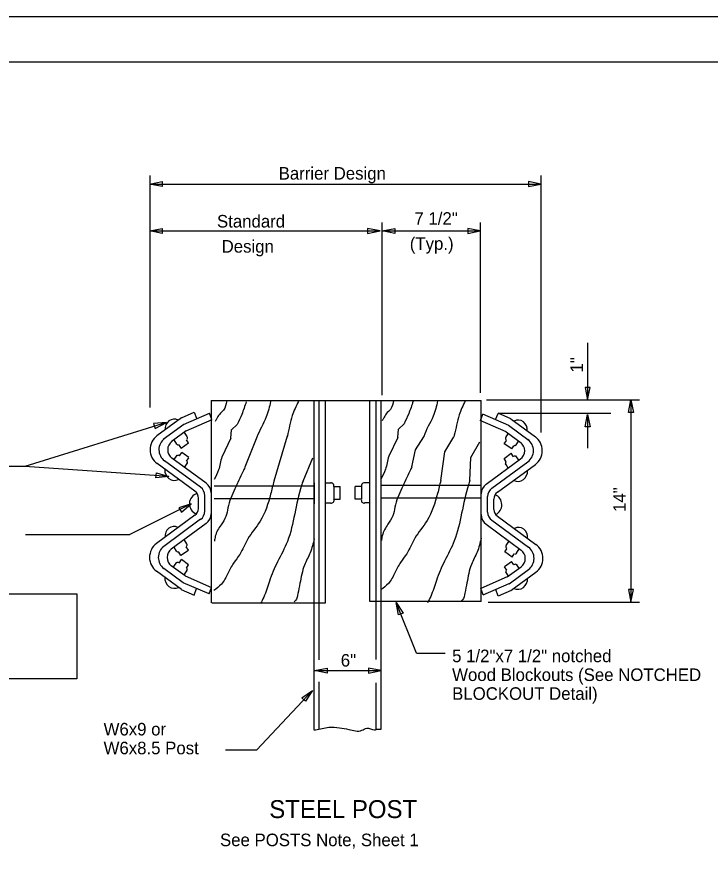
# Model space of a CAD drawing. Extents: x 0 to 34, y 0 to 22.
# Drawn here: x 11.64 to 19.37, y 12.6 to 22 of the extents above; entities that cross this region are included whole.
import ezdxf

# ---------------------------------------------------------------- set-up
doc = ezdxf.new("R2010")
doc.units = 0
for name, color, linetype in [('SH_Border', 7, 'Continuous'), ('SH_Cut_Line', 7, 'Continuous'), ('ST_Details', 7, 'Continuous'), ('ST_Text', 7, 'Continuous')]:
    doc.layers.add(name, color=color, linetype=linetype)

msp = doc.modelspace()

# ---------------------------------------------------------------- linework, layer by layer
at = {"layer": 'SH_Border'}
msp.add_lwpolyline([(2, 21.5), (33.5, 21.5), (33.5, 0.5), (2, 0.5)], close=True, dxfattribs=at)
at = {"layer": 'SH_Cut_Line'}
msp.add_lwpolyline([(0, 0), (34, 0), (34, 22), (0, 22)], close=True, dxfattribs=at)
at = {"layer": 'ST_Details'}
for p, q in [((13.8045, 17.7204), (16.8155, 17.7204)), ((13.8045, 17.7204), (13.8045, 15.4639)), ((14.9532, 15.4641), (14.9532, 17.7132)), ((15.0099, 15.4641), (15.0099, 17.7132)), ((15.0807, 15.4641), (15.0807, 17.7132)), ((15.5737, 15.4784), (15.5737, 17.7179)), ((15.6445, 15.4784), (15.6445, 17.7179)), ((15.7012, 15.4784), (15.7012, 17.7179)), ((16.8112, 17.7204), (16.8112, 15.4782)), ((13.4719, 17.5269), (13.6158, 17.5897)), ((13.6433, 17.5196), (13.6163, 17.5889)), ((13.4722, 17.5266), (13.1992, 17.3266)), ((13.4967, 17.4539), (13.7861, 17.5802)), ((13.5258, 17.3834), (13.8154, 17.5096)), ((13.8122, 17.5101), (13.7852, 17.5792)), ((17.0938, 17.3726), (16.8043, 17.4989)), ((16.8074, 17.4992), (16.8344, 17.5686)), ((17.1231, 17.4431), (16.8336, 17.5694)), ((16.9764, 17.5089), (17.0034, 17.5781)), ((17.1478, 17.5161), (17.0038, 17.5789)), ((17.1475, 17.5157), (17.4204, 17.3157)), ((13.4992, 17.4554), (13.2692, 17.2867)), ((14.0938, 17.4547), (14.0315, 17.3941)), ((15.8855, 17.3072), (15.8937, 17.4012)), ((15.9561, 17.4619), (15.8937, 17.4012)), ((17.1205, 17.4446), (17.3506, 17.2759)), ((13.525, 17.3829), (13.3583, 17.2607)), ((13.5364, 17.3182), (13.5062, 17.3656)), ((14.0233, 17.3001), (14.0315, 17.3941)), ((14.3129, 17.3119), (14.1808, 16.9761)), ((14.6532, 17.3251), (14.5026, 16.8231)), ((15.8855, 17.3072), (15.7845, 17.1011)), ((17.0891, 17.3096), (17.1192, 17.3569)), ((17.0947, 17.3721), (17.2614, 17.2499)), ((13.4207, 17.2357), (13.3915, 17.2814)), ((13.4693, 17.1892), (13.4462, 17.2256)), ((13.4692, 17.1897), (13.5517, 17.2482)), ((13.5516, 17.2482), (13.5289, 17.2837)), ((14.0233, 17.3001), (13.9212, 17.0892)), ((17.1563, 17.1811), (17.0737, 17.2397)), ((17.0738, 17.2396), (17.0965, 17.2751)), ((17.1561, 17.1807), (17.1792, 17.2169)), ((17.2048, 17.2271), (17.2339, 17.2727)), ((13.4509, 17.1034), (13.4756, 17.1421)), ((13.5541, 17.0844), (13.4754, 17.1419)), ((17.0714, 17.0757), (17.1501, 17.1332)), ((17.1745, 17.0947), (17.1498, 17.1334)), ((13.686, 16.7546), (13.2821, 17.0491)), ((13.7492, 16.7996), (13.3645, 17.0799)), ((13.391, 17.0631), (13.4227, 17.1131)), ((13.509, 16.9771), (13.54, 17.0256)), ((13.5299, 17.0459), (13.5537, 17.0834)), ((14.8283, 16.8231), (14.9367, 17.0819)), ((16.8705, 16.7889), (17.2552, 17.0692)), ((16.9337, 16.7439), (17.3376, 17.0382)), ((17.0956, 17.0372), (17.0717, 17.0749)), ((17.2345, 17.0544), (17.2027, 17.1044)), ((13.6228, 16.7096), (13.1997, 17.0181)), ((16.9969, 16.6989), (17.4201, 17.0072)), ((17.1164, 16.9684), (17.0855, 17.0171)), ((14.9487, 16.7654), (13.8367, 16.7654)), ((14.9547, 16.5689), (14.9547, 16.8014)), ((15.0792, 16.8028), (15.1477, 16.8028)), ((15.1715, 16.7619), (15.2442, 16.7619)), ((15.1715, 16.7619), (15.1725, 16.6218)), ((15.2442, 16.6218), (15.2442, 16.7619)), ((15.4088, 16.6218), (15.4088, 16.7609)), ((15.4816, 16.7619), (15.4098, 16.7619)), ((15.4816, 16.7619), (15.4805, 16.6218)), ((15.5737, 16.8028), (15.5054, 16.8028)), ((16.8109, 16.7724), (15.699, 16.7724)), ((13.732, 16.4887), (13.732, 16.6619)), ((16.8169, 16.4482), (16.8169, 16.6807)), ((16.8877, 16.4779), (16.8877, 16.6511)), ((13.6612, 16.5181), (13.6612, 16.6324)), ((13.732, 16.5699), (13.732, 16.5807)), ((14.9487, 16.6253), (13.8364, 16.6253)), ((15.0792, 16.5783), (15.1388, 16.5783)), ((15.1725, 16.6218), (15.2442, 16.6218)), ((15.4805, 16.6218), (15.4088, 16.6218)), ((15.5737, 16.5783), (15.5142, 16.5783)), ((16.8109, 16.6323), (15.6986, 16.6323)), ((16.8877, 16.5592), (16.8877, 16.5699)), ((16.9585, 16.5072), (16.9585, 16.6217)), ((13.623, 16.4409), (13.1927, 16.1256)), ((13.6862, 16.3962), (13.2751, 16.0947)), ((16.9335, 16.3854), (17.3446, 16.0839)), ((16.9967, 16.4302), (17.4271, 16.1147)), ((13.7495, 16.3512), (13.3577, 16.0641)), ((16.8702, 16.3404), (17.262, 16.0532)), ((13.4182, 16.0409), (13.3892, 16.0866)), ((13.5341, 16.1236), (13.5039, 16.1709)), ((13.5492, 16.0534), (13.5266, 16.0889)), ((17.0947, 16.1031), (17.1248, 16.1504)), ((13.467, 15.9946), (13.4438, 16.0309)), ((13.4668, 15.9949), (13.5493, 16.0536)), ((17.162, 15.9744), (17.0794, 16.0331)), ((17.0795, 16.0329), (17.1022, 16.0684)), ((17.1617, 15.9741), (17.1849, 16.0104)), ((17.2105, 16.0204), (17.2396, 16.0661)), ((13.3886, 15.8684), (13.4203, 15.9184)), ((13.4486, 15.9087), (13.4732, 15.9474)), ((13.5517, 15.8897), (13.473, 15.9472)), ((17.0771, 15.8692), (17.1557, 15.9267)), ((17.1802, 15.8882), (17.1555, 15.9269)), ((17.2402, 15.8479), (17.2084, 15.8979)), ((13.4725, 15.6132), (13.193, 15.8169)), ((13.4932, 15.6892), (13.2755, 15.8479)), ((13.5153, 15.7642), (13.3579, 15.8789)), ((13.5067, 15.7822), (13.5377, 15.8309)), ((13.5275, 15.8512), (13.5514, 15.8887)), ((17.1012, 15.8307), (17.0773, 15.8682)), ((17.1221, 15.7617), (17.0912, 15.8104)), ((17.1043, 15.7534), (17.2617, 15.8681)), ((17.1264, 15.6784), (17.3442, 15.8371)), ((17.1472, 15.6024), (17.4267, 15.8061)), ((13.5153, 15.7646), (13.8091, 15.6366)), ((17.1043, 15.7537), (16.8107, 15.6257)), ((13.4702, 15.6141), (13.6142, 15.5512)), ((13.7811, 15.5634), (13.4917, 15.6897)), ((13.6132, 15.5516), (13.6416, 15.6242)), ((13.7802, 15.5634), (13.809, 15.6371)), ((16.8394, 15.5526), (16.8107, 15.6262)), ((16.8386, 15.5526), (17.1281, 15.6789)), ((17.0064, 15.5409), (16.9781, 15.6134)), ((17.1495, 15.6032), (17.0056, 15.5406)), ((13.8095, 15.4641), (15.0807, 15.4641)), ((14.9532, 14.0519), (14.9532, 15.4641)), ((15.0099, 14.8304), (15.0099, 15.4641)), ((16.8155, 15.4784), (15.5737, 15.4784)), ((15.6445, 14.8326), (15.6445, 15.4784)), ((15.7012, 14.0566), (15.7012, 15.4784)), ((15.0099, 14.0519), (15.0099, 14.5829)), ((15.6445, 14.0566), (15.6445, 14.5742))]:
    msp.add_line(p, q, dxfattribs=at)
for points in [[(16.043, 16.9832), (16.0821, 17.1722), (16.1742, 17.3162)], [(16.3647, 16.8301), (16.4097, 17.1497), (16.5112, 17.3162)], [(16.6906, 16.8301), (16.701, 17.0854), (16.799, 17.2589)]]:
    msp.add_lwpolyline(points, dxfattribs=at)
for centre, major_axis, start_param, end_param in [((13.3919, 17.4076), (0, -0.1065), 2.687211, 4.851441), ((17.2278, 17.3968), (0, -0.1065), 1.431744, 3.595974), ((13.3001, 17.1724), (0, -0.1875), 3.747084, 5.680264), ((13.5205, 17.3058), (0, 0.0198), 3.70437, 5.352473), ((17.1049, 17.2972), (0, 0.0198), 0.930712, 2.578815), ((17.3196, 17.1616), (0, -0.1875), 0.602921, 2.536101), ((13.3624, 17.1725), (0, -0.15), 3.747137, 5.680324), ((13.4248, 17.1726), (0, -0.1125), 3.747102, 5.680297), ((13.4335, 17.2463), (0, -0.0195), 5.247458, 6.879592), ((17.192, 17.2377), (0, -0.0195), 5.686779, 7.318912), ((17.1949, 17.1618), (0, -0.1125), 0.602888, 2.536083), ((17.2573, 17.1617), (0, -0.15), 0.602861, 2.536048), ((13.4352, 17.0899), (0, 0.021), 5.452301, 7.118326), ((13.5208, 17.0274), (0, 0.021), 4.196406, 5.73538), ((17.1046, 17.0188), (0, 0.021), 0.547805, 2.086779), ((17.1903, 17.0813), (0, 0.021), 5.448045, 7.11407), ((13.3951, 16.9451), (0, -0.115), 4.640651, 6.714317), ((17.2246, 16.9343), (0, -0.115), 5.852054, 7.925719), ((13.6257, 16.662), (0, 0.1125), 4.712389, 5.68034), ((13.6789, 16.6916), (0, 0.1312), 4.712389, 5.680267), ((15.146, 16.7733), (0, -0.0298), 2.729343, 3.43401), ((15.1449, 16.7725), (0, 0.03), 4.35702, 6.237266), ((15.146, 16.7733), (0, -0.0298), 1.431351, 1.439211), ((15.5081, 16.7725), (0, 0.03), 0.045919, 1.926166), ((15.507, 16.7733), (0, -0.0298), 4.843974, 4.851834), ((15.507, 16.7733), (0, -0.0298), 2.849176, 3.553842), ((16.9408, 16.6808), (0, 0.1312), 0.602918, 1.570796), ((16.994, 16.6512), (0, 0.1125), 0.602846, 1.570796), ((13.6719, 16.5699), (0, -0.1171), 3.363241, 5.976631), ((13.5726, 16.6324), (0, 0.0937), 4.712389, 5.680377), ((17.0471, 16.6216), (0, 0.0937), 0.602808, 1.570796), ((16.9331, 16.5587), (0, -0.1192), 0.40519, 2.779828), ((15.1438, 16.6101), (0, -0.0326), 6.093782, 8.224205), ((15.5092, 16.6101), (0, -0.0326), 4.342165, 6.472589), ((13.5726, 16.5181), (0, -0.0937), 0.605563, 1.570796), ((13.6257, 16.4886), (0, -0.1125), 0.605651, 1.570796), ((13.6789, 16.4591), (0, -0.1312), 0.605566, 1.570796), ((16.994, 16.4778), (0, -0.1125), 4.712389, 5.677535), ((17.0471, 16.5073), (0, -0.0937), 4.712389, 5.677623), ((16.9408, 16.4483), (0, -0.1312), 4.712389, 5.677619), ((13.3888, 16.2107), (0, -0.1065), 2.687211, 4.851441), ((17.2309, 16.1999), (0, -0.1065), 1.431744, 3.595974), ((13.2934, 15.9714), (0, -0.1875), 3.747091, 5.68028), ((13.3558, 15.9715), (0, -0.15), 3.747115, 5.680355), ((13.5182, 16.1111), (0, 0.0198), 3.70437, 5.352473), ((17.1106, 16.0906), (0, 0.0198), 0.930712, 2.578815), ((17.264, 15.9607), (0, -0.15), 0.602831, 2.53607), ((17.3263, 15.9606), (0, -0.1875), 0.602905, 2.536094), ((13.4182, 15.9716), (0, -0.1125), 3.747102, 5.680258), ((13.4311, 16.0516), (0, -0.0195), 5.247458, 6.879592), ((17.1976, 16.0311), (0, -0.0195), 5.686779, 7.318912), ((17.2015, 15.9608), (0, -0.1125), 0.602927, 2.536083), ((13.4328, 15.8952), (0, 0.021), 5.452301, 7.118326), ((17.196, 15.8747), (0, 0.021), 5.448045, 7.11407), ((13.5185, 15.8327), (0, 0.021), 4.196406, 5.73538), ((17.1103, 15.8122), (0, 0.021), 0.547805, 2.086779), ((13.3951, 15.7418), (0, -0.115), 4.640651, 6.714317), ((17.2246, 15.731), (0, -0.115), 5.852054, 7.925719)]:
    msp.add_ellipse(centre, major_axis=major_axis, ratio=0.944544, start_param=start_param, end_param=end_param, dxfattribs=at)
for points in [[(13.977, 17.7161), (13.9407, 17.6152), (13.8952, 17.5671), (13.8635, 17.5142), (13.8472, 17.4884)], [(14.195, 17.7066), (14.145, 17.5671), (14.0938, 17.4547)], [(14.4674, 17.7114), (14.4175, 17.5382), (14.3131, 17.3122), (14.3119, 17.3091)], [(14.7762, 17.7114), (14.7081, 17.5527), (14.6536, 17.3267), (14.6489, 17.3091)], [(15.8392, 17.7232), (15.8029, 17.6224), (15.7574, 17.5742), (15.7257, 17.5214), (15.7095, 17.4956)], [(16.0572, 17.7137), (16.0072, 17.5742), (15.9561, 17.4619)], [(16.3297, 17.7186), (16.2797, 17.5454), (16.1752, 17.3194), (16.1742, 17.3162)], [(16.6384, 17.7186), (16.5703, 17.5599), (16.5158, 17.3339), (16.5112, 17.3162)], [(13.9223, 17.0939), (13.9044, 17.0191), (13.8862, 16.9469), (13.8362, 16.8412)], [(15.7845, 17.1011), (15.7666, 17.0262), (15.7484, 16.9541), (15.6984, 16.8482)], [(14.1808, 16.9761), (14.1587, 16.9277), (14.0677, 16.7354), (13.9907, 16.5239), (13.968, 16.4277), (13.9135, 16.3364), (13.8499, 16.2067), (13.8407, 16.1537)], [(16.043, 16.9832), (16.0208, 16.9349), (15.93, 16.7426), (15.8528, 16.5311), (15.8302, 16.4349), (15.7757, 16.3436), (15.7121, 16.2137), (15.703, 16.1609)], [(14.5026, 16.8231), (14.4674, 16.6777), (14.3494, 16.3749), (14.2132, 16.1777), (14.1222, 16.0047), (14.0542, 15.9086), (13.9907, 15.7932), (13.918, 15.6731), (13.8317, 15.6009)], [(14.8283, 16.8231), (14.8125, 16.7739), (14.7352, 16.4566), (14.6536, 16.1489), (14.5446, 15.9231), (14.4537, 15.7066), (14.3902, 15.5287), (14.3539, 15.4567)], [(16.3647, 16.8301), (16.3297, 16.6849), (16.2116, 16.3821), (16.0753, 16.1849), (15.9845, 16.0119), (15.9164, 15.9157), (15.8528, 15.8004), (15.7802, 15.6802), (15.6939, 15.6081)], [(16.6906, 16.8301), (16.6747, 16.7811), (16.5975, 16.4637), (16.5158, 16.1561), (16.4068, 15.9302), (16.316, 15.7137), (16.2524, 15.5359), (16.2162, 15.4639)], [(14.9532, 16.1777), (14.9079, 16.0241), (14.8442, 15.8846), (14.7944, 15.6826), (14.7717, 15.5672), (14.7444, 15.4902), (14.7307, 15.4759)], [(16.8155, 16.1849), (16.7702, 16.0311), (16.7065, 15.8917), (16.6566, 15.6897), (16.6338, 15.5744), (16.6067, 15.4974), (16.593, 15.4831)], [(14.9503, 14.0496), (14.969, 14.0502), (15.1172, 14.0771), (15.2352, 14.0722), (15.3397, 14.0531), (15.485, 14.0434), (15.5395, 14.0674), (15.6258, 14.0482), (15.6657, 14.0566), (15.7012, 14.0566)]]:
    msp.add_spline(points, degree=3, dxfattribs=at)
at = {"layer": 'ST_Text'}
for p, q in [((13.1181, 20.2294), (13.1182, 17.6452)), ((17.4818, 20.2294), (17.4818, 17.3636)), ((13.1161, 20.1349), (17.4818, 20.1349)), ((15.7064, 19.7074), (15.7064, 17.7811)), ((16.8052, 19.7074), (16.8052, 17.8052)), ((13.1177, 19.6129), (13.6959, 19.6129)), ((13.6959, 19.6129), (15.6893, 19.6129)), ((15.7121, 19.6129), (16.0798, 19.6129)), ((16.0798, 19.6129), (16.8052, 19.6129)), ((18.0021, 18.3635), (18.0021, 17.7281)), ((16.8747, 17.7281), (18.5807, 17.7281)), ((18.4862, 17.7281), (18.4862, 17.0224)), ((17.0038, 17.5789), (18.2621, 17.5789)), ((18.0021, 17.5662), (18.0021, 17.1912)), ((13.3303, 16.8739), (11.7236, 16.9862)), ((18.4862, 17.0224), (18.4862, 15.4734)), ((13.5814, 16.5672), (12.8962, 16.2255)), ((11.7312, 16.2255), (12.8962, 16.2255)), ((16.0947, 14.9026), (15.8677, 15.4704)), ((16.8926, 15.4734), (18.5807, 15.4734)), ((16.0947, 14.9026), (16.4156, 14.9026)), ((14.9532, 14.7091), (15.6984, 14.7091)), ((14.9569, 14.7091), (15.1444, 14.7091)), ((14.3082, 13.8227), (14.9325, 14.4876)), ((14.3082, 13.8227), (13.9654, 13.8227))]:
    msp.add_line(p, q, dxfattribs=at)
for points in [[(13.2561, 20.1069), (13.1161, 20.1349), (13.2561, 20.1629)], [(17.3418, 20.1069), (17.4818, 20.1349), (17.3418, 20.1629)], [(13.2577, 19.5849), (13.1177, 19.6129), (13.2577, 19.6409)], [(15.5493, 19.5849), (15.6893, 19.6129), (15.5493, 19.6409)], [(15.8521, 19.5849), (15.7121, 19.6129), (15.8521, 19.6409)], [(16.6652, 19.5849), (16.8052, 19.6129), (16.6652, 19.6409)], [(17.9741, 17.8681), (18.0021, 17.7281), (18.0301, 17.8681)], [(18.4582, 17.5881), (18.4862, 17.7281), (18.5142, 17.5881)], [(17.9741, 17.4262), (18.0021, 17.5662), (18.0301, 17.4262)], [(13.1775, 17.4101), (13.3044, 17.4756), (13.1621, 17.4639)], [(13.194, 16.9164), (13.3303, 16.8739), (13.1881, 16.8607)], [(13.471, 16.4768), (13.5814, 16.5672), (13.4447, 16.5262)], [(18.4582, 15.6134), (18.4862, 15.4734), (18.5142, 15.6134)], [(9.5197, 15.5651), (12.3046, 15.5651), (12.3046, 14.6162), (9.5197, 14.6162)], [(15.8942, 15.3301), (15.8677, 15.4704), (15.9461, 15.3511)], [(15.0969, 14.6811), (14.9569, 14.7091), (15.0969, 14.7371)], [(15.5584, 14.6811), (15.6984, 14.7091), (15.5584, 14.7371)], [(14.8151, 14.4063), (14.9325, 14.4876), (14.8554, 14.3674)]]:
    msp.add_lwpolyline(points, close=True, dxfattribs=at)
msp.add_lwpolyline([(13.3044, 17.4756), (11.7236, 16.9862), (11.4729, 16.9862)], dxfattribs=at)

# ---------------------------------------------------------------- texts
for s, rotation, p in [('Barrier Design', 360, (14.5566, 20.1851)), ('Standard', 360, (13.8685, 19.6506)), (' 7 1/2"', 360, (16.0193, 19.6816)), (' Design', 360, (13.8685, 19.3706)), ('(Typ.)', 360, (16.0193, 19.4016)), ('1" ', 90, (17.951, 18.0337)), ('14" ', 90, (18.4287, 16.4783)), ('6" ', 360, (15.2495, 14.7539)), ('5 1/2"x7 1/2" notched', 360, (16.4917, 14.8031)), ('Wood Blockouts (See NOTCHED', 360, (16.4917, 14.5931)), ('BLOCKOUT Detail)', 360, (16.4917, 14.3831)), ('W6x9 or', 360, (12.6039, 13.9858)), ('W6x8.5 Post', 360, (12.6039, 13.7758)), ('See POSTS Note, Sheet 1', 360, (13.9025, 12.7508))]:
    msp.add_text(s, height=0.14, rotation=rotation, dxfattribs=at).set_placement(p)
msp.add_text('STEEL POST', height=0.2, dxfattribs=at).set_placement((14.4517, 13.0641))

doc.saveas('drawing.dxf')
